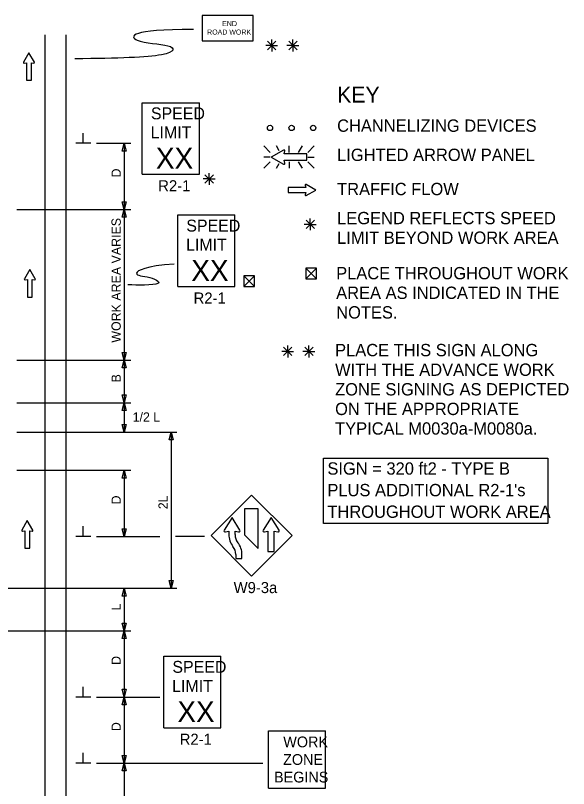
# Model space of a CAD drawing. Extents: x 16732 to 18482, y 5716 to 6919.
# Drawn here: x 17007 to 17424, y 6335 to 6919 of the extents above; entities that cross this region are included whole.
import ezdxf

# ---------------------------------------------------------------- set-up
doc = ezdxf.new("R2010")
doc.units = 0
for name, color, linetype in [('MT_SCRATCH_LEVEL_E', 7, 'Continuous'), ('PAVT_EDGE_EX', 7, 'Continuous'), ('TRAFFIC_SIGNS_PR', 7, 'Continuous'), ('TYPICAL_TEXT_DIMEN_EX', 7, 'Continuous'), ('TYPICAL_TEXT_DIMEN_PR', 7, 'Continuous')]:
    doc.layers.add(name, color=color, linetype=linetype)

msp = doc.modelspace()

# ---------------------------------------------------------------- linework, layer by layer
at = {"layer": 'MT_SCRATCH_LEVEL_E'}
for p, q in [((17016.71, 6890.89), (17012.6, 6883.65)), ((17020.85, 6883.65), (17016.71, 6890.89)), ((17013.08, 6882.96), (17014.85, 6883.28)), ((17014.85, 6883.28), (17014.85, 6870.02)), ((17018.6, 6870.02), (17018.6, 6883.28)), ((17018.6, 6883.28), (17020.38, 6882.96)), ((17014.85, 6870.02), (17018.6, 6870.02)), ((17225.75, 6789.04), (17212.49, 6789.04)), ((17212.49, 6789.04), (17212.49, 6785.3)), ((17225.43, 6790.81), (17225.75, 6789.04)), ((17233.36, 6787.19), (17226.12, 6791.3)), ((17212.49, 6785.3), (17225.75, 6785.3)), ((17225.75, 6785.3), (17225.43, 6783.52)), ((17226.12, 6783.04), (17233.36, 6787.19)), ((17017.44, 6727.27), (17013.33, 6720.03)), ((17021.59, 6720.03), (17017.44, 6727.27)), ((17013.81, 6719.34), (17015.59, 6719.66)), ((17015.59, 6719.66), (17015.59, 6706.4)), ((17019.33, 6706.4), (17019.33, 6719.66)), ((17019.33, 6719.66), (17021.11, 6719.34)), ((17015.59, 6706.4), (17019.33, 6706.4)), ((17015.53, 6537.59), (17011.42, 6530.35)), ((17019.68, 6530.35), (17015.53, 6537.59)), ((17011.9, 6529.66), (17013.68, 6529.98)), ((17013.68, 6529.98), (17013.68, 6516.72)), ((17017.42, 6516.72), (17017.42, 6529.98)), ((17017.42, 6529.98), (17019.2, 6529.66)), ((17013.68, 6516.72), (17017.42, 6516.72))]:
    msp.add_line(p, q, dxfattribs=at)
for centre, start, end in [((17013, 6883.42), 150.42484, 279.96381), ((17020.44, 6883.42), 260.03619, 29.77312), ((17225.89, 6790.89), 60.42484, 189.96381), ((17225.89, 6783.45), 170.03619, 299.77312), ((17013.74, 6719.8), 150.42484, 279.96381), ((17021.18, 6719.8), 260.03619, 29.77312), ((17011.83, 6530.12), 150.42484, 279.96381), ((17019.27, 6530.12), 260.03619, 29.77312)]:
    msp.add_arc(centre, 0.463, start, end, dxfattribs=at)
at = {"layer": 'PAVT_EDGE_EX'}
for p, q in [((17028.68, 6904.41), (17028.68, 6086.27)), ((17044.68, 6904.41), (17044.68, 6086.27))]:
    msp.add_line(p, q, dxfattribs=at)
at = {"layer": 'TRAFFIC_SIGNS_PR'}
for p, q in [((17102.4, 6853.1), (17145.6, 6853.1)), ((17102.4, 6799.1), (17102.4, 6853.1)), ((17145.6, 6799.1), (17145.6, 6853.1)), ((17194.1, 6820.57), (17199.03, 6815.64)), ((17205.86, 6816.75), (17203.65, 6820.57)), ((17213.18, 6815.64), (17213.18, 6820.57)), ((17220.42, 6815.64), (17223.27, 6820.57)), ((17227.33, 6815.64), (17232.27, 6820.57)), ((17199.03, 6812.08), (17194.1, 6812.08)), ((17227.33, 6812.08), (17232.27, 6812.08)), ((17194.1, 6803.59), (17199.03, 6808.52)), ((17203.61, 6803.59), (17205.72, 6807.25)), ((17213.18, 6808.52), (17213.18, 6803.59)), ((17223.31, 6803.59), (17220.46, 6808.52)), ((17227.33, 6808.52), (17232.27, 6803.59)), ((17102.4, 6799.1), (17145.6, 6799.1)), ((17129.11, 6768.35), (17172.31, 6768.35)), ((17129.11, 6714.35), (17129.11, 6768.35)), ((17172.31, 6714.35), (17172.31, 6768.35)), ((17129.11, 6714.35), (17172.31, 6714.35)), ((17184.93, 6556.84), (17154.39, 6526.29)), ((17215.48, 6526.29), (17184.93, 6556.84)), ((17179.63, 6546.46), (17179.63, 6526.89)), ((17189.99, 6546.46), (17179.63, 6546.46)), ((17189.99, 6516.53), (17189.99, 6546.46)), ((17154.39, 6526.29), (17184.93, 6495.74)), ((17179.63, 6526.89), (17189.99, 6516.53)), ((17184.93, 6495.74), (17215.48, 6526.29)), ((17118.61, 6435.23), (17161.81, 6435.23)), ((17118.61, 6381.23), (17118.61, 6435.23)), ((17161.81, 6381.23), (17161.81, 6435.23)), ((17118.61, 6381.23), (17161.81, 6381.23)), ((17197.58, 6335.68), (17197.58, 6378.88)), ((17197.58, 6378.88), (17240.78, 6378.88)), ((17240.78, 6335.68), (17240.78, 6378.88)), ((17197.58, 6335.68), (17240.78, 6335.68))]:
    msp.add_line(p, q, dxfattribs=at)
msp.add_lwpolyline([(17147.71, 6899.8), (17186.11, 6899.8), (17186.11, 6919), (17147.71, 6919)], close=True, dxfattribs=at)
for points in [[(17209.11, 6817.36), (17199.82, 6812.08), (17209.11, 6806.76)], [(17209.98, 6807.39), (17209.58, 6809.65), (17226.6, 6809.65), (17226.6, 6814.46), (17209.58, 6814.46), (17209.99, 6816.74)], [(17176.15, 6530.46), (17170.16, 6539.87), (17164.16, 6530.46)], [(17205.65, 6530.46), (17199.66, 6539.87), (17193.67, 6530.46)], [(17165.21, 6529.04), (17167.79, 6529.75), (17167.79, 6527.24)], [(17172.51, 6527.12), (17172.51, 6529.75), (17175.1, 6529.04)], [(17194.72, 6529.04), (17197.3, 6529.75), (17197.3, 6514.22), (17202.02, 6514.22), (17202.02, 6529.75), (17204.61, 6529.04)], [(17172.93, 6512.1), (17172.93, 6509.12), (17177.65, 6509.12), (17177.65, 6512.1)]]:
    msp.add_lwpolyline(points, dxfattribs=at)
for centre in [(17198.82, 6834.11), (17215.12, 6834.11), (17231.42, 6834.11)]:
    msp.add_circle(centre, 2, dxfattribs=at)
for centre, radius, start, end in [((17209.4, 6816.83), 0.598, 350.73078, 118.89165), ((17209.4, 6807.28), 0.597, 241.48329, 9.95933), ((17164.96, 6529.95), 0.945, 147.52044, 285.3986), ((17181.95, 6526.82), 14.17, 178.32933, 218.54273), ((17181.95, 6526.82), 9.45, 178.19356, 218.54646), ((17160.7, 6527.49), 11.81, 358.18937, 0.00483), ((17175.35, 6529.95), 0.947, 254.68281, 32.2708), ((17171.98, 6517.64), 11.81, 74.67996, 74.68078), ((17186.11, 6536.79), 11.81, 212.45689, 212.46649), ((17194.47, 6529.95), 0.946, 147.54971, 285.33159), ((17204.86, 6529.95), 0.943, 254.67777, 32.46648), ((17215.62, 6536.79), 11.81, 212.45689, 212.46649), ((17163.48, 6512.1), 14.17, 0, 38.5422), ((17163.48, 6512.1), 9.45, 0, 38.54567)]:
    msp.add_arc(centre, radius, start, end, dxfattribs=at)
at = {"layer": 'TYPICAL_TEXT_DIMEN_EX'}
msp.add_lwpolyline([(17239.16, 6584.71), (17408.62, 6584.71), (17408.62, 6535.51), (17239.16, 6535.51)], close=True, dxfattribs=at)
at = {"layer": 'TYPICAL_TEXT_DIMEN_PR'}
for p, q in [((17196.91, 6899.51), (17203.29, 6893.13)), ((17203.29, 6899.51), (17196.91, 6893.13)), ((17200.1, 6896.32), (17200.1, 6900.77)), ((17219.35, 6899.51), (17212.97, 6893.13)), ((17212.98, 6899.51), (17219.35, 6893.13)), ((17216.16, 6896.32), (17216.16, 6900.77)), ((17200.1, 6896.32), (17195.57, 6896.32)), ((17200.1, 6896.32), (17203.29, 6896.32)), ((17200.1, 6896.32), (17204.58, 6896.32)), ((17200.1, 6896.32), (17200.1, 6891.82)), ((17216.16, 6896.32), (17211.63, 6896.32)), ((17216.16, 6896.32), (17219.35, 6896.32)), ((17216.16, 6896.32), (17220.64, 6896.32)), ((17216.16, 6896.32), (17216.16, 6891.82)), ((17057.8, 6822.46), (17057.8, 6830.24)), ((17063.43, 6822.46), (17052.18, 6822.46)), ((17067.68, 6822.46), (17093.68, 6822.46)), ((17087.11, 6816.6), (17088.68, 6822.46)), ((17088.68, 6822.46), (17088.68, 6772.46)), ((17088.68, 6822.46), (17090.25, 6816.6)), ((17088.68, 6816.6), (17087.11, 6816.6)), ((17090.25, 6816.6), (17088.68, 6816.6)), ((17152.85, 6795.54), (17152.85, 6800)), ((17152.85, 6795.54), (17148.32, 6795.54)), ((17156.04, 6798.73), (17149.66, 6792.35)), ((17149.67, 6798.73), (17156.04, 6792.35)), ((17152.85, 6795.54), (17156.04, 6795.54)), ((17152.85, 6795.54), (17157.33, 6795.54)), ((17152.85, 6795.54), (17152.85, 6791.04)), ((17088.68, 6772.46), (17087.11, 6778.32)), ((17087.11, 6778.32), (17088.68, 6778.32)), ((17088.68, 6778.32), (17090.25, 6778.32)), ((17090.25, 6778.32), (17088.68, 6772.46)), ((17007.61, 6772.46), (17093.68, 6772.46)), ((17087.11, 6766.6), (17088.68, 6772.46)), ((17088.68, 6772.46), (17088.68, 6658.73)), ((17088.68, 6772.46), (17090.25, 6766.6)), ((17088.68, 6766.6), (17087.11, 6766.6)), ((17090.25, 6766.6), (17088.68, 6766.6)), ((17229.24, 6761.27), (17229.24, 6765.73)), ((17229.24, 6761.27), (17224.7, 6761.27)), ((17226.05, 6764.46), (17232.42, 6758.08)), ((17232.42, 6764.46), (17226.05, 6758.08)), ((17229.24, 6761.27), (17232.42, 6761.27)), ((17229.24, 6761.27), (17233.71, 6761.27)), ((17229.24, 6761.27), (17229.24, 6756.77)), ((17225.85, 6728.21), (17233.85, 6720.21)), ((17225.85, 6720.21), (17233.85, 6728.21)), ((17179.06, 6722.36), (17187.06, 6714.36)), ((17179.06, 6714.36), (17187.06, 6722.36)), ((17215.38, 6668.54), (17209, 6662.17)), ((17209.01, 6668.54), (17215.38, 6662.17)), ((17212.19, 6665.36), (17212.19, 6669.81)), ((17225.07, 6668.54), (17231.44, 6662.17)), ((17231.44, 6668.54), (17225.07, 6662.17)), ((17228.25, 6665.36), (17228.25, 6669.81)), ((17088.68, 6658.73), (17087.11, 6664.59)), ((17087.11, 6664.59), (17088.68, 6664.59)), ((17088.68, 6664.59), (17090.25, 6664.59)), ((17090.25, 6664.59), (17088.68, 6658.73)), ((17212.19, 6665.36), (17207.66, 6665.36)), ((17212.19, 6665.36), (17215.38, 6665.36)), ((17212.19, 6665.36), (17216.67, 6665.36)), ((17212.19, 6665.36), (17212.19, 6660.86)), ((17228.25, 6665.36), (17223.72, 6665.36)), ((17228.25, 6665.36), (17231.44, 6665.36)), ((17228.25, 6665.36), (17232.73, 6665.36)), ((17228.25, 6665.36), (17228.25, 6660.86)), ((17007.61, 6658.73), (17093.68, 6658.73)), ((17087.11, 6652.87), (17088.68, 6658.73)), ((17088.68, 6658.73), (17088.68, 6626.65)), ((17088.68, 6658.73), (17090.25, 6652.87)), ((17088.68, 6652.87), (17087.11, 6652.87)), ((17090.25, 6652.87), (17088.68, 6652.87)), ((17088.68, 6626.65), (17087.11, 6632.52)), ((17087.11, 6632.52), (17088.68, 6632.52)), ((17088.68, 6633.75), (17088.68, 6630.15)), ((17088.68, 6632.52), (17090.25, 6632.52)), ((17090.25, 6632.52), (17088.68, 6626.65)), ((17007.61, 6626.65), (17093.68, 6626.65)), ((17087.11, 6620.79), (17088.68, 6626.65)), ((17088.68, 6626.65), (17088.68, 6604.41)), ((17088.68, 6626.65), (17090.25, 6620.79)), ((17088.68, 6620.79), (17087.11, 6620.79)), ((17090.25, 6620.79), (17088.68, 6620.79)), ((17088.68, 6604.41), (17087.11, 6610.27)), ((17087.11, 6610.27), (17088.68, 6610.27)), ((17088.68, 6610.27), (17090.25, 6610.27)), ((17090.25, 6610.27), (17088.68, 6604.41)), ((17007.61, 6604.41), (17128.49, 6604.41)), ((17122.58, 6598.55), (17124.15, 6604.41)), ((17124.15, 6604.41), (17124.15, 6486.53)), ((17124.15, 6604.41), (17125.72, 6598.55)), ((17124.15, 6598.55), (17122.58, 6598.55)), ((17125.72, 6598.55), (17124.15, 6598.55)), ((17007.61, 6575.6), (17093.68, 6575.6)), ((17087.11, 6569.74), (17088.68, 6575.6)), ((17088.68, 6575.6), (17088.68, 6525.6)), ((17088.68, 6575.6), (17090.25, 6569.74)), ((17088.68, 6569.74), (17087.11, 6569.74)), ((17090.25, 6569.74), (17088.68, 6569.74)), ((17057.8, 6525.6), (17057.8, 6533.39)), ((17088.68, 6525.6), (17087.11, 6531.47)), ((17087.11, 6531.47), (17088.68, 6531.47)), ((17088.68, 6531.47), (17090.25, 6531.47)), ((17090.25, 6531.47), (17088.68, 6525.6)), ((17063.43, 6525.6), (17052.18, 6525.6)), ((17067.68, 6525.6), (17115.65, 6525.6)), ((17149.32, 6525.6), (17127.39, 6525.6)), ((17124.15, 6486.53), (17122.58, 6492.39)), ((17122.58, 6492.39), (17124.15, 6492.39)), ((17124.15, 6492.39), (17125.72, 6492.39)), ((17125.72, 6492.39), (17124.15, 6486.53)), ((16984.43, 6486.53), (17128.49, 6486.53)), ((17087.11, 6480.67), (17088.68, 6486.53)), ((17088.68, 6486.53), (17088.68, 6454.43)), ((17088.68, 6486.53), (17090.25, 6480.67)), ((17088.68, 6480.67), (17087.11, 6480.67)), ((17090.25, 6480.67), (17088.68, 6480.67)), ((17088.68, 6454.43), (17087.11, 6460.29)), ((17087.11, 6460.29), (17088.68, 6460.29)), ((17088.68, 6460.29), (17090.25, 6460.29)), ((17090.25, 6460.29), (17088.68, 6454.43)), ((16965.08, 6454.43), (17093.68, 6454.43)), ((17087.11, 6448.57), (17088.68, 6454.43)), ((17088.68, 6454.43), (17088.68, 6404.43)), ((17088.68, 6454.43), (17090.25, 6448.57)), ((17088.68, 6448.57), (17087.11, 6448.57)), ((17090.25, 6448.57), (17088.68, 6448.57)), ((17057.8, 6404.43), (17057.8, 6412.21)), ((17088.68, 6404.43), (17087.11, 6410.29)), ((17087.11, 6410.29), (17088.68, 6410.29)), ((17088.68, 6410.29), (17090.25, 6410.29)), ((17090.25, 6410.29), (17088.68, 6404.43)), ((17063.43, 6404.43), (17052.18, 6404.43)), ((17067.68, 6404.43), (17115.73, 6404.43)), ((17087.11, 6398.57), (17088.68, 6404.43)), ((17088.68, 6404.43), (17090.25, 6398.57)), ((17088.68, 6404.43), (17088.68, 6354.43)), ((17088.68, 6398.57), (17087.11, 6398.57)), ((17090.25, 6398.57), (17088.68, 6398.57)), ((17057.8, 6354.43), (17057.8, 6362.21)), ((17088.68, 6354.43), (17087.11, 6360.29)), ((17087.11, 6360.29), (17088.68, 6360.29)), ((17088.68, 6360.29), (17090.25, 6360.29)), ((17090.25, 6360.29), (17088.68, 6354.43)), ((17063.43, 6354.43), (17052.18, 6354.43)), ((17067.68, 6354.43), (17193.44, 6354.43)), ((17087.11, 6348.57), (17088.68, 6354.43)), ((17088.68, 6354.43), (17088.68, 6304.43)), ((17088.68, 6354.43), (17090.25, 6348.57)), ((17088.68, 6348.57), (17087.11, 6348.57)), ((17090.25, 6348.57), (17088.68, 6348.57))]:
    msp.add_line(p, q, dxfattribs=at)
for points in [[(17225.85, 6728.21), (17225.85, 6720.21), (17233.85, 6720.21), (17233.85, 6728.21)], [(17179.06, 6722.36), (17179.06, 6714.36), (17187.06, 6714.36), (17187.06, 6722.36)]]:
    msp.add_lwpolyline(points, close=True, dxfattribs=at)
for points in [[(17141.08, 6908.49), (17092.61, 6908.49), (17092.61, 6897.74), (17127.53, 6897.74), (17127.53, 6888.08), (17084.67, 6886.56), (17051.51, 6886.3)], [(17126.53, 6731.12), (17104.79, 6730.08), (17092.18, 6722.46), (17108.48, 6722.46), (17122.28, 6714.48), (17092.87, 6715.54), (17091.33, 6715.59)]]:
    msp.add_open_spline(points, degree=3, dxfattribs=at)

# ---------------------------------------------------------------- texts
at = {"layer": 'TRAFFIC_SIGNS_PR'}
for s, height, p in [('END', 3.831, (17162.71, 6910.93)), ('ROAD WORK', 3.831, (17151.32, 6904.54)), ('SPEED', 9, (17108.88, 6840.57)), ('LIMIT', 9, (17108.7, 6826.17)), ('XX', 15.785, (17112.65, 6803.33)), ('R2-1', 8.37, (17114.41, 6786.23)), ('SPEED', 9, (17135.6, 6755.82)), ('LIMIT', 9, (17135.42, 6741.42)), ('XX', 15.785, (17139.36, 6718.58)), ('PLACE THROUGHOUT WORK', 9.3, (17248.79, 6719.78)), ('AREA AS INDICATED IN THE', 9.3, (17248.79, 6704.98)), ('R2-1', 8.37, (17141.12, 6701.48)), ('NOTES.', 9.3, (17248.79, 6690.18)), ('PLACE THIS SIGN ALONG', 9.3, (17247.97, 6661.71)), ('WITH THE ADVANCE WORK', 9.3, (17247.97, 6646.91)), ('ZONE SIGNING AS DEPICTED', 9.3, (17247.97, 6632.11)), ('ON THE APPROPRIATE', 9.3, (17247.97, 6617.31)), ('TYPICAL M0030a-M0080a.', 9.3, (17247.97, 6602.51)), ('W9-3a', 8.37, (17171.36, 6482.87)), ('SPEED', 9, (17125.1, 6422.69)), ('LIMIT', 9, (17124.91, 6408.29)), ('XX', 15.785, (17128.86, 6385.45)), ('R2-1', 8.37, (17130.62, 6368.36)), ('WORK', 8.119, (17208.83, 6366.47)), ('ZONE', 8.119, (17208.69, 6353.18)), ('BEGINS', 8.119, (17201.86, 6339.9))]:
    msp.add_text(s, height=height, dxfattribs=at).set_placement(p)
at = {"layer": 'TYPICAL_TEXT_DIMEN_EX'}
for s, height, p in [('KEY', 12, (17249.5, 6853.22)), ('CHANNELIZING DEVICES', 9.3, (17249.5, 6831.17)), ('LIGHTED ARROW PANEL', 9.3, (17249.5, 6809.12)), ('TRAFFIC FLOW', 9.3, (17249.5, 6783.32)), ('LEGEND REFLECTS SPEED', 9.3, (17249.5, 6761.37)), ('LIMIT BEYOND WORK AREA', 9.3, (17249.5, 6746.57)), ('SIGN = 320 ft2 - TYPE B', 9.3, (17242.17, 6572.3)), ("PLUS ADDITIONAL R2-1's", 9.3, (17242.17, 6556)), ('THROUGHOUT WORK AREA', 9.3, (17242.17, 6539.7))]:
    msp.add_text(s, height=height, dxfattribs=at).set_placement(p)
at = {"layer": 'TYPICAL_TEXT_DIMEN_PR'}
for s, p in [('D', (17086.12, 6796.68)), ('WORK AREA VARIES', (17086.12, 6671.95)), ('B', (17086.12, 6641.93)), ('D', (17086.12, 6549.82)), ('2L', (17121.6, 6546.19)), ('L', (17086.12, 6469.84)), ('D', (17086.12, 6428.65)), ('D', (17086.12, 6378.65))]:
    msp.add_text(s, height=7, rotation=90, dxfattribs=at).set_placement(p)
msp.add_text('1/2 L', height=7, dxfattribs=at).set_placement((17095.08, 6612.32))

doc.saveas('drawing.dxf')
